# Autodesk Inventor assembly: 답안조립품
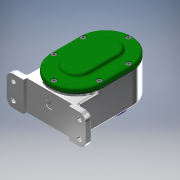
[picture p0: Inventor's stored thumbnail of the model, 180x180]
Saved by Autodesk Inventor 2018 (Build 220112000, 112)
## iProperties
Created: 2021-05
Part Number: 답안조립품
Material: 일반
Document SubType Name: Assembly
Designer: Admin
Author: Admin
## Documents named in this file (19)
- C:\Users\Admin\Desktop\710509V1001\답안조립품.iam
- C:\Users\Admin\Desktop\710509V1001\답안부품1.ipt
- C:\Users\Admin\Desktop\710509V1001\축 A.ipt
- C:\Users\Admin\Desktop\710509V1001\베어링 6001.ipt
- 베어링 6001.ipt
- C:\Users\Admin\Desktop\710509V1001\베어링 6002.ipt
- 베어링 6002.ipt
- C:\Users\Admin\Desktop\710509V1001\칼라.ipt
- C:\Users\Admin\Desktop\710509V1001\키 5 x 5 x 12.ipt
- C:\Users\Admin\Desktop\710509V1001\스퍼기어 A.ipt
- C:\Users\Admin\Desktop\710509V1001\축 B.ipt
- C:\Users\Admin\Desktop\710509V1001\스퍼기어 B.ipt
- C:\Users\Admin\Desktop\710509V1001\키 4 x 4 x 12.ipt
- C:\Users\Admin\Desktop\710509V1001\개스킷 A.ipt
- C:\Users\Admin\Desktop\710509V1001\개스킷 B.ipt
- C:\Users\Admin\Desktop\710509V1001\커버 A.ipt
- C:\Users\Admin\Desktop\710509V1001\커버 B.ipt
- C:\Users\Admin\Desktop\710509V1001\볼트 M4.ipt
- C:\Users\Admin\Desktop\710509V1001\오일 실 12 22 7.ipt
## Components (2 placed, 2 different names)
1. 개스킷 A:1
2. 개스킷 B:1
